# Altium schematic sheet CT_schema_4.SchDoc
size 296 x 173 mm
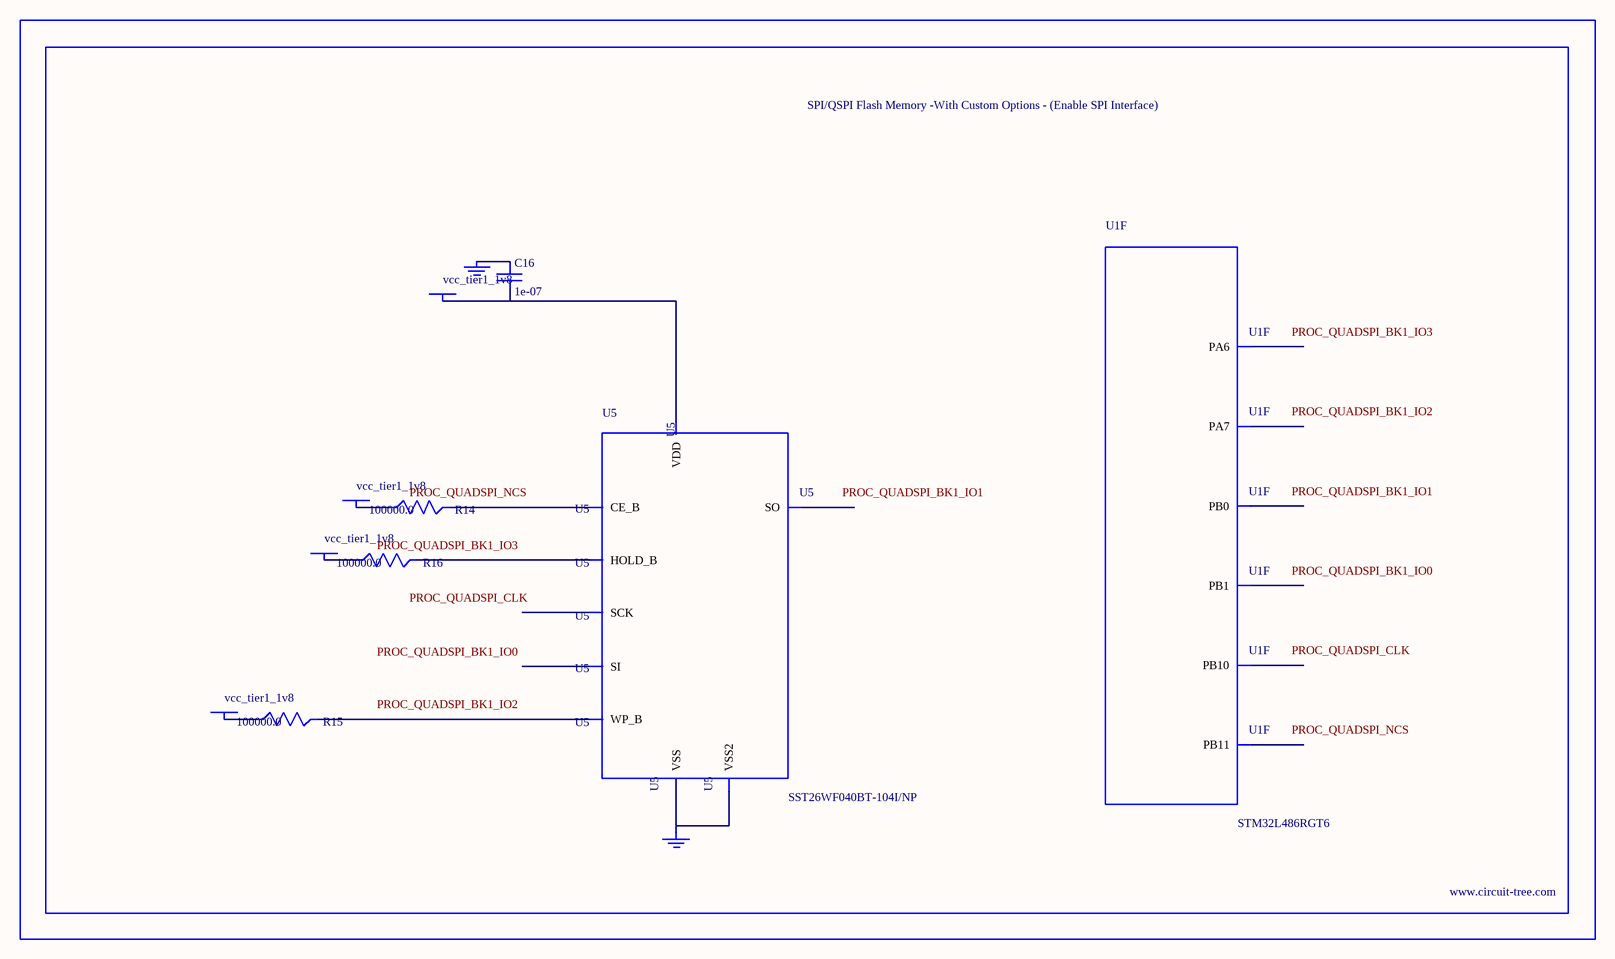
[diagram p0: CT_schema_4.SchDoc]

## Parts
BORDER3  (no value)
C16  1e-07  [C0402]
GND_INSTANCE_3_0  (no value)
GND_INSTANCE_3_1  (no value)
POWER_INSTANCE_3_0  vcc_tier1_1v8
POWER_INSTANCE_3_1  vcc_tier1_1v8
POWER_INSTANCE_3_2  vcc_tier1_1v8
POWER_INSTANCE_3_3  vcc_tier1_1v8
R14  100000.0  [R0603]
R15  100000.0  [R0603]
R16  100000.0  [R0603]
U1  STM32L486RGT6  [LQFP64]  (part F of 7)
U5  SST26WF040BT-104I/NP  [USON-8]

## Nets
NetC16_1: C16.1 GND_INSTANCE_3_0.0(GND)
NetC16_2: C16.2 POWER_INSTANCE_3_3.0(PWR) U5.8(VDD)
NetGND_INSTANCE_3_1_0: GND_INSTANCE_3_1.0(GND) U5.4(VSS) U5.9(VSS2)
NetPOWER_INSTANCE_3_0_0: POWER_INSTANCE_3_0.0(PWR) R14.1
NetPOWER_INSTANCE_3_1_0: POWER_INSTANCE_3_1.0(PWR) R15.1
NetPOWER_INSTANCE_3_2_0: POWER_INSTANCE_3_2.0(PWR) R16.1
NetR14_2: R14.2 U5.1(CE_B)
NetR15_2: R15.2 U5.3(WP_B)
NetR16_2: R16.2 U5.7(HOLD_B)

Not connected (* = marked no-connect by the designer): U1 22(PA6) 23(PA7) 26(PB0) 27(PB1) 29(PB10) 30(PB11); U5 2(SO) 5(SI) 6(SCK)

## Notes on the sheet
- Labels drawn without touching a wire or pin: PROC_QUADSPI_BK1_IO0, PROC_QUADSPI_BK1_IO1, PROC_QUADSPI_BK1_IO2, PROC_QUADSPI_BK1_IO3, PROC_QUADSPI_CLK, PROC_QUADSPI_NCS

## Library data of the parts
BORDER3 = BORDER_PAGE3
C16 = C0402C104K3RACTU
GND_INSTANCE_3_0 GND_INSTANCE_3_1 = GND
POWER_INSTANCE_3_0-POWER_INSTANCE_3_3 = PWR
R14-R16 = RC0603JR-07100KL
